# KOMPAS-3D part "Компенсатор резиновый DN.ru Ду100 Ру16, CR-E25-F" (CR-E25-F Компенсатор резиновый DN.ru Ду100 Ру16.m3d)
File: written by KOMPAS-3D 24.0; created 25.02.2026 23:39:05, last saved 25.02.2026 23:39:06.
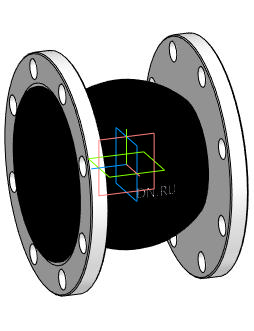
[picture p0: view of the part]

Document properties: Автор: DN.RU; Полное имя файла: D:\PROJECT CAD\DN.RU\...178(4)(ACTUALE). CR-E25-F Компенсатор резиновый DN.ru Ру10-16\DN100_PN16\CR-E25-F Компенсатор резиновый DN.ru Ду100 Ру16.m3d

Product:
- Body: Твердое тело2  | qty 1
    Масса: 11.528562
- Part/product: Компенсатор резиновый DN.ru Ду100 Ру16  | designation CR-E25-F
    Масса: 7.88
    Раздел спецификации: Прочие изделия
    Комментарий: D140-02176
    Примечание: D140-02176
    additional columns: Типовые

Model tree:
1. Твердое тело2  (labels: Твердое тело2)

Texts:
  CR-E25-F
